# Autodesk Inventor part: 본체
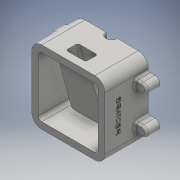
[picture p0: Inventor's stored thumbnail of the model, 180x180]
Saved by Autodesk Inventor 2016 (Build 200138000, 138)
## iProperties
Created: 2018-01
Part Number: 본체
Material: 일반
Document SubType Name: Modeling
Designer: 605-03
Density: 1 g/cm^3
Appearance: 기본값
Author: 605-03
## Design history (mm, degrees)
sketch "스케치2"
  geometry: L1 (40, 55)-(-40, 55); L2 (-55, 40)-(-55, -40); L3 (-40, -55)-(40, -55); L4 (55, -40)-(55, 40); L5 (55, 55)-(-55, -55); L6 (-55, 55)-(55, -55); L7 (40, -45)-(-40, -45); L8 (-45, -40)-(-45, 40); L9 (-40, 45)-(40, 45); L10 (45, 40)-(45, -40); A1 r 5 centre (40, -40) between (40, -45) and (45, -40); A2 r 5 centre (40, 40) between (45, 40) and (40, 45); A3 r 5 centre (-40, 40) between (-40, 45) and (-45, 40); A4 r 5 centre (-40, -40) between (-45, -40) and (-40, -45); A5 r 15 centre (40, -40) between (40, -55) and (55, -40); A6 r 15 centre (40, 40) between (55, 40) and (40, 55); A7 r 15 centre (-40, 40) between (-40, 55) and (-55, 40); A8 r 15 centre (-40, -40) between (-55, -40) and (-40, -55); 1 further point
  constraints: 20 end point, 16 point on circle, 16 tangent, 8 centre point, 8 point on line, 6 equal radius, 4 parallel, 2 midpoint, 2 perpendicular, 1 horizontal, 3 other
  dimensions: "d0" = 110 distance of L6.end L5.end; "d1" = 110 distance of L5.end L6.start; "d2" = 10 distance between parallel lines of L3 L7; "d3" = 5 radius of A1; "d4" = 15 radius of A5
extrude "돌출1" new body sketch "스케치2" stored distance "d5" = 65; taper "d6" = 0 deg
sketch "스케치3"
  geometry: L1 (-32.5, -45)-(32.5, -45) reference; L2 (32.5, -45)-(32.5, -55) reference; L3 (32.5, -55)-(-32.5, -55) reference; L4 (-32.5, -55)-(-32.5, -45) reference; L5 (32.5, 45)-(-32.5, 45) reference; L6 (-32.5, 45)-(-32.5, 55) reference; L7 (-32.5, 55)-(32.5, 55) reference; L8 (32.5, 55)-(32.5, 45) reference; L9 (-32.5, -45)-(32.5, -45) reference; L10 (-32.5, 40)-(32.5, 40) reference; L11 (-32.5, -40)-(-32.5, 40) reference; L12 (32.5, -40)-(-32.5, -40) reference; L13 (32.5, 40)-(32.5, -40) reference; L14 (32.5, -40)-(-32.5, -40) reference; L15 (-32.5, -45)-(-32.5, -40) reference; L16 (-32.5, -45)-(32.5, -45) reference; L17 (32.5, -40)-(32.5, -45) reference; L18 (32.5, -40)-(32.5, 40) reference; L19 (32.5, -35)-(-2.5, -35); L20 (-2.5, -35)-(-23.936, 45); L21 (-32.5, 45)-(32.5, 45) reference; L22 (-23.936, 45)-(32.5, 45); L23 (32.5, 45)-(32.5, -35); 1 further point
  constraints: 8 end point, 2 collinear, 2 point on line, 1 horizontal
  dimensions: "d7" = 105 deg angle of L19 L20; "d8" = 20 distance between parallel lines of L3 L19; "d9" = 30 distance from line of L11 L19.end
extrude "돌출2" join sketch "스케치3" stored distance "d10" = 50; taper "d11" = 0 deg
sketch "스케치4"
  geometry: L1 (32.5, -35)-(-2.5, -35) reference; L2 (-2.5, -35)-(-23.936, 45) reference; L3 (-23.936, 45)-(-32.5, 45) reference; L4 (-32.5, 45)-(-32.5, 55) reference; L5 (-32.5, 55)-(32.5, 55) reference; L6 (32.5, 55)-(32.5, -35) reference; L7 (-32.5, -45)-(32.5, -45) reference; L8 (32.5, -45)-(32.5, -55) reference; L9 (32.5, -55)-(-32.5, -55) reference; L10 (-32.5, -55)-(-32.5, -45) reference; L11 (-32.5, 55)-(32.5, 55) reference; L12 (25, 55)-(25, 36); L13 (25, 36)-(17.5, 36); L14 (16.5, 35)-(16.5, 22); L15 (16.5, 22)-(13.5, 22); L16 (12.5, 21)-(12.5, -24); L17 (13.5, -25)-(17.5, -25); L18 (17.5, -25)-(17.5, -29); L19 (18.5, -30)-(32.5, -30); L20 (25, 55)-(32.5, 55); L21 (32.5, -35)-(-2.5, -35) reference; L22 (-2.5, -35)-(-23.936, 45) reference; L23 (-23.936, 45)-(-32.5, 45) reference; L24 (-32.5, 45)-(-32.5, 55) reference; L25 (-32.5, 55)-(32.5, 55) reference; L26 (32.5, 55)-(32.5, -35) reference; L27 (-32.5, -45)-(32.5, -45) reference; L28 (32.5, -45)-(32.5, -55) reference; L29 (32.5, -55)-(-32.5, -55) reference; L30 (-32.5, -55)-(-32.5, -45) reference; L31 (32.5, 45)-(-23.936, 45) reference; L32 (32.5, 45)-(32.5, -35) reference; L33 (32.5, -35)-(-2.5, -35) reference; L34 (-2.5, -35)-(-23.936, 45) reference; L35 (32.5, 55)-(32.5, -30); A1 r 1 centre (17.5, 35) between (17.5, 36) and (16.5, 35); A2 r 1 centre (13.5, 21) between (13.5, 22) and (12.5, 21); A3 r 1 centre (13.5, -24) between (12.5, -24) and (13.5, -25); A4 r 1 centre (18.5, -29) between (17.5, -29) and (18.5, -30); 5 further points
  constraints: 20 end point, 9 point on line, 8 point on circle, 8 tangent, 7 perpendicular, 4 centre point, 3 equal radius, 2 horizontal, 1 collinear
  dimensions: "d12" = 15 diameter of L12 L35; "d13" = 32 diameter of L14 L35; "d14" = 40 diameter of L16 L35; "d15" = 30 diameter of L18 L35; "d16" = 19 distance of L12.start L12.end; "d17" = 14 distance of point (16.5, 36) L14.end; "d18" = 47 distance of point (12.5, 22) point (12.5, -25); "d19" = 5 distance of L17.end point (17.5, -30); "d20" = 1 radius of A1
revolve "회전1" sketch "스케치4" stored, may be unused: angle "d21" = 90 deg
sketch "스케치5"
  geometry: L1 (25, 55)-(25, 36) reference; L2 (25, 36)-(17.5, 36) reference; L3 (16.5, 35)-(16.5, 22) reference; L4 (16.5, 22)-(13.5, 22) reference; L5 (12.5, 21)-(12.5, -24) reference; L6 (13.5, -25)-(17.5, -25) reference; L7 (17.5, -25)-(17.5, -29) reference; L8 (18.5, -30)-(32.5, -30) reference; L9 (32.5, -30)-(32.5, -35) reference; L10 (32.5, -35)-(-2.5, -35) reference; L11 (-2.5, -35)-(-23.936, 45) reference; L12 (-23.936, 45)-(-32.5, 45) reference; L13 (-32.5, 45)-(-32.5, 55) reference; L14 (-32.5, 55)-(25, 55) reference; L15 (32.5, -45)-(32.5, -55) reference; L16 (32.5, -55)-(-32.5, -55) reference; L17 (-32.5, -55)-(-32.5, -45) reference; L18 (-32.5, -45)-(32.5, -45) reference; L19 (-32.5, 55)-(32.5, 55) reference; L20 (-21.439, 55)-(-1.343, -20); L21 (-3.439, 55)-(6.743, 17); L22 (20.306, -20)-(-1.343, -20); L23 (20.306, 17)-(6.743, 17); L24 (-32.5, -40)-(-32.5, 40) reference; L25 (25, 55)-(25, 36) reference; L26 (25, 36)-(17.5, 36) reference; L27 (16.5, 35)-(16.5, 22) reference; L28 (16.5, 22)-(13.5, 22) reference; L29 (12.5, 21)-(12.5, -24) reference; L30 (13.5, -25)-(17.5, -25) reference; L31 (17.5, -25)-(17.5, -29) reference; L32 (18.5, -30)-(32.5, -30) reference; L33 (32.5, -30)-(32.5, -35) reference; L34 (32.5, -35)-(-2.5, -35) reference; L35 (-2.5, -35)-(-23.936, 45) reference; L36 (-23.936, 45)-(-32.5, 45) reference; L37 (-32.5, 45)-(-32.5, 55) reference; L38 (-32.5, 55)-(25, 55) reference; L39 (32.5, -45)-(32.5, -55) reference; L40 (32.5, -55)-(-32.5, -55) reference; L41 (-32.5, -55)-(-32.5, -45) reference; L42 (-32.5, -45)-(32.5, -45) reference; L43 (32.5, 21)-(32.5, -24) reference; L44 (32.5, 21)-(32.5, 21) reference; L45 (32.5, -24)-(32.5, 21) reference; L46 (32.5, -24)-(32.5, -24) reference; L47 (20.306, 17)-(20.306, -20); A1 r 1 centre (17.5, 35) between (17.5, 36) and (16.5, 35) reference; A2 r 1 centre (13.5, 21) between (13.5, 22) and (12.5, 21) reference; A3 r 1 centre (13.5, -24) between (12.5, -24) and (13.5, -25) reference; A4 r 1 centre (18.5, -29) between (17.5, -29) and (18.5, -30) reference; A5 r 6 centre (18.5, -29) between (12.572, -29.928) and (12.584, -30); A6 r 1 centre (17.5, 35) between (17.5, 36) and (16.5, 35) reference; A7 r 1 centre (13.5, 21) between (13.5, 22) and (12.5, 21) reference; A8 r 1 centre (13.5, -24) between (12.5, -24) and (13.5, -25) reference; A9 r 1 centre (18.5, -29) between (17.5, -29) and (18.5, -30) reference; 1 further point
  constraints: 10 end point, 2 horizontal, 2 point on circle, 2 point on line, 1 centre point, 1 perpendicular
  dimensions: "d24" = 5 distance between parallel lines of L11 L20 (derived); "d25" = 75 deg angle of L19 L21; "d26" = 18 distance of L20.start L21.start; "d27" = 37 distance between parallel lines of L22 L23; "d29" = 5 distance between parallel lines of L22 L6; "d31" = 11.06095 distance of L13.end L20.start
extrude "돌출3" cut sketch "스케치5" stored distance "d32" = 30; taper "d33" = 0 deg
sketch "스케치6"
  geometry: L1 (-45, 40)-(-45, -40) reference; L2 (-40, -45)-(-25, -45) reference; L3 (-25, -45)-(-25, 35) reference; L4 (-25, 35)-(25, 35) reference; L5 (25, 35)-(25, -45) reference; L6 (25, -45)-(40, -45) reference; L7 (45, -40)-(45, 40) reference; L8 (40, 45)-(-40, 45) reference; L9 (-40, 55)-(40, 55) reference; L10 (55, 40)-(55, -40) reference; L11 (40, -55)-(7.5, -55) reference; L12 (7.5, -55)-(7.5, -36) reference; L13 (7.5, -36)-(15, -36) reference; L14 (16, -35)-(16, -22) reference; L15 (16, -22)-(19, -22) reference; L16 (20, -21)-(20, 24) reference; L17 (19, 25)-(15, 25) reference; L18 (15, 25)-(15, 29) reference; L19 (14, 30)-(-14, 30) reference; L20 (-15, 29)-(-15, 25) reference; L21 (-15, 25)-(-19, 25) reference; L22 (-20, 24)-(-20, -21) reference; L23 (-19, -22)-(-16, -22) reference; L24 (-16, -22)-(-16, -35) reference; L25 (-15, -36)-(-7.5, -36) reference; L26 (-7.5, -36)-(-7.5, -55) reference; L27 (-7.5, -55)-(-40, -55) reference; L28 (-55, -40)-(-55, 40) reference; L29 (-65, -20.5)-(-55, -20.5); L30 (-65, -35.5)-(-55, -35.5); L31 (-65, 35.5)-(-55, 35.5); L32 (-65, 20.5)-(-55, 20.5); L33 (55, -20.5)-(65, -20.5); L34 (55, -35.5)-(65, -35.5); L35 (55, 20.5)-(65, 20.5); L36 (55, 35.5)-(65, 35.5); L37 (-55, -35.5)-(-55, -20.5); L38 (-55, 20.5)-(-55, 35.5); L39 (55, 20.5)-(55, 35.5); L40 (55, -35.5)-(55, -20.5); L41 (55, -40)-(55, 40) reference; A1 r 5 centre (-40, 40) between (-40, 45) and (-45, 40) reference; A2 r 5 centre (-40, -40) between (-45, -40) and (-40, -45) reference; A3 r 5 centre (40, -40) between (40, -45) and (45, -40) reference; A4 r 5 centre (40, 40) between (45, 40) and (40, 45) reference; A5 r 15 centre (-40, 40) between (-40, 55) and (-55, 40) reference; A6 r 15 centre (40, 40) between (55, 40) and (40, 55) reference; A7 r 15 centre (40, -40) between (40, -55) and (55, -40) reference; A8 r 1 centre (15, -35) between (15, -36) and (16, -35) reference; A9 r 1 centre (19, -21) between (19, -22) and (20, -21) reference; A10 r 1 centre (19, 24) between (20, 24) and (19, 25) reference; A11 r 1 centre (14, 29) between (15, 29) and (14, 30) reference; A12 r 1 centre (-14, 29) between (-14, 30) and (-15, 29) reference; A13 r 1 centre (-19, 24) between (-19, 25) and (-20, 24) reference; A14 r 1 centre (-19, -21) between (-20, -21) and (-19, -22) reference; A15 r 1 centre (-15, -35) between (-16, -35) and (-15, -36) reference; A16 r 15 centre (-40, -40) between (-55, -40) and (-40, -55) reference; A17 r 7.5 centre (-65, -28) between (-65, -20.5) and (-65, -35.5); A18 r 7.5 centre (-65, 28) between (-65, 35.5) and (-65, 20.5); A19 r 7.5 centre (65, -28) between (65, -35.5) and (65, -20.5); A20 r 7.5 centre (65, 28) between (65, 20.5) and (65, 35.5); 1 further point
  constraints: 24 end point, 8 horizontal, 8 point on circle, 8 point on line, 8 tangent, 4 centre point, 4 collinear
  dimensions: "d34" = 15 diameter of A17; "d35" = 27 distance from line of L27 A17.centre; "d36" = 10 distance from line of A17.centre L28; "d37" = 15 diameter of A18; "d38" = 10 distance from line of L28 A18.centre; "d39" = 27 distance from line of L9 A18.centre; "d40" = 15 diameter of A19; "d41" = 15 diameter of A20; "d42" = 10 distance from line of A19.centre L10; "d43" = 27 distance from line of L11 A19.centre; "d44" = 27 distance from line of L9 A20.centre; "d45" = 10 distance from line of L10 A20.centre
extrude "돌출4" join sketch "스케치6" distance "d46" = 20; taper "d47" = 0 deg
hole "구멍1" diameter "d50" = 3.242; stored, may be unused: countersink angle "d54" = 90 deg, drill point angle "d56" = 118 deg; dims "d51" = 9, "d52" = 4, "d53" = 2, "d55" = 11, "d77" = 10, "d78" = 10
hole "구멍2" diameter "d59" = 3.242; stored, may be unused: countersink angle "d63" = 90 deg, drill point angle "d65" = 118 deg; dims "d60" = 9, "d61" = 4, "d62" = 2, "d64" = 11, "d75" = 10, "d76" = 10
hole "구멍3" diameter "d68" = 3.242; stored, may be unused: countersink angle "d72" = 90 deg, drill point angle "d74" = 118 deg; dims "d69" = 9, "d70" = 4, "d71" = 2, "d73" = 11, "d79" = 10, "d80" = 10
hole "구멍4" diameter "d83" = 3.242; stored, may be unused: countersink angle "d87" = 90 deg, drill point angle "d89" = 118 deg; dims "d81" = 10, "d82" = 10, "d84" = 9, "d85" = 4, "d86" = 2, "d88" = 11
sketch "스케치7"
  geometry: L1 (80, 0)-(0, 0) reference; L2 (-15, 0)-(-15, 65) reference; 2 further points
  constraints: 1 other
  dimensions: "d90" = 20 distance from line of L1 point (40, 20); "d91" = 55 distance from line of L2 point (40, 20)
feature "엠보싱1" sketch "스케치7" dims "d92" = 0.5, "d93" = 0
fillet "모깎기1" dims "d94" = 3
fillet "모깎기2" dims "d95" = 3
chamfer "모따기1" distance "d96" = 1; stored, may be unused: second distance "d97" = 2, angle "d98" = 45 deg
chamfer "모따기2" distance "d99" = 1; stored, may be unused: second distance "d100" = 2, angle "d101" = 45 deg
node "솔리드1"
node "투영된 루프1"
node "투영된 루프2"
node "투영된 루프3"
node "투영된 루프4"
node "절단 모서리 투영1"
node "절단 모서리 투영2"
node "절단 모서리 투영3"
node "절단 모서리 투영4"
node "절단 모서리 투영5"
node "절단 모서리 투영6"
